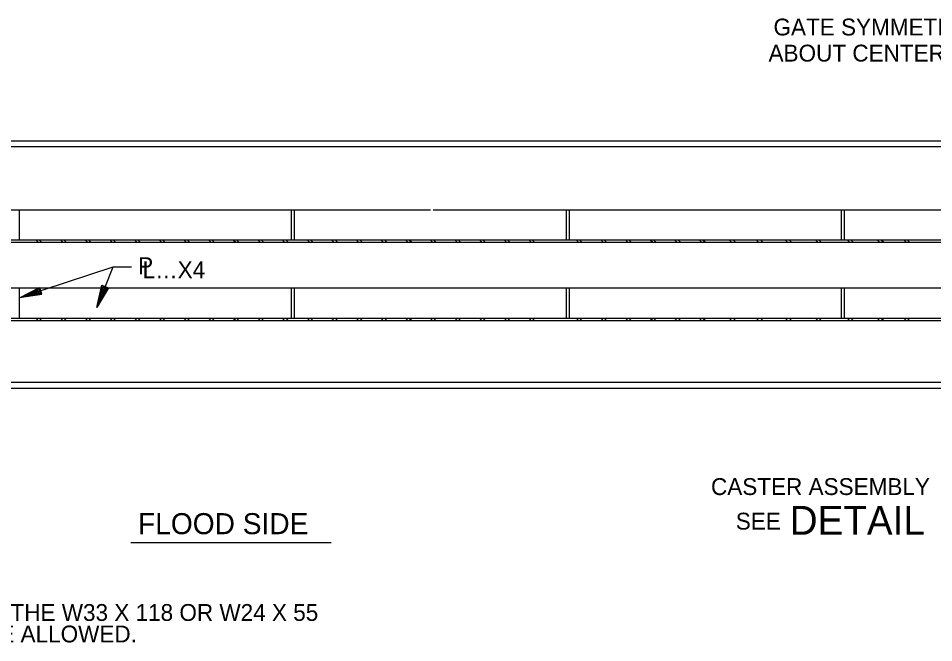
# Model space of a CAD drawing. Extents: x 0 to 53.3, y -2.9 to 37.3.
# Drawn here: x 33.49 to 43.64, y 11.84 to 18.76 of the extents above; entities that cross this region are included whole.
import ezdxf

# ---------------------------------------------------------------- set-up
doc = ezdxf.new("R2010")
doc.units = 0
for name, color, linetype in [('Level 2', 7, 'Continuous'), ('Level 25', 7, 'Continuous'), ('Level 3', 7, 'Continuous'), ('Level 44', 7, 'Continuous'), ('Level 50', 7, 'Continuous')]:
    doc.layers.add(name, color=color, linetype=linetype)

msp = doc.modelspace()

# ---------------------------------------------------------------- linework, layer by layer
at = {"layer": 'Level 2'}
for p, q in [((47.128, 17.401), (11.078, 17.401)), ((47.128, 17.338), (13.38, 17.338)), ((38.062, 16.635), (33.094, 16.635)), ((33.503, 16.302), (33.503, 16.635)), ((35.635, 16.635), (35.604, 16.635)), ((36.522, 16.302), (36.522, 16.635)), ((36.553, 16.302), (36.553, 16.635)), ((45.687, 16.635), (38.094, 16.635)), ((39.572, 16.302), (39.572, 16.635)), ((39.603, 16.302), (39.603, 16.635)), ((40.802, 16.635), (40.771, 16.635)), ((42.622, 16.302), (42.622, 16.635)), ((42.653, 16.302), (42.653, 16.635)), ((43.26, 16.635), (43.229, 16.635)), ((47.128, 16.302), (13.047, 16.302)), ((47.128, 16.276), (13.047, 16.276)), ((47.128, 15.77), (13.016, 15.77)), ((33.503, 15.436), (33.503, 15.77)), ((36.522, 15.436), (36.522, 15.77)), ((36.553, 15.436), (36.553, 15.77)), ((39.572, 15.436), (39.572, 15.77)), ((39.603, 15.436), (39.603, 15.77)), ((42.622, 15.436), (42.622, 15.77)), ((42.653, 15.436), (42.653, 15.77)), ((47.128, 15.436), (13.047, 15.436)), ((47.128, 15.41), (13.016, 15.41)), ((47.128, 14.724), (11.109, 14.724)), ((47.128, 14.661), (11.078, 14.661))]:
    msp.add_line(p, q, dxfattribs=at)
at = {"layer": 'Level 3'}
for p, q in [((34.54, 16.002), (34.362, 15.557)), ((34.362, 15.557), (34.362, 15.557)), ((34.388, 15.621), (34.388, 15.621))]:
    msp.add_line(p, q, dxfattribs=at)
msp.add_lwpolyline([(34.493, 15.773), (34.362, 15.557), (34.416, 15.804), (34.482, 15.778), (34.388, 15.621), (34.425, 15.789), (34.467, 15.772), (34.413, 15.683), (34.433, 15.774), (34.451, 15.767), (34.438, 15.748)], dxfattribs=at)
at = {"layer": 'Level 44'}
for p, q in [((33.715, 16.276), (33.689, 16.302)), ((33.753, 16.276), (33.727, 16.302)), ((33.988, 16.276), (33.962, 16.302)), ((34.026, 16.276), (34, 16.302)), ((34.262, 16.276), (34.236, 16.302)), ((34.3, 16.276), (34.274, 16.302)), ((34.535, 16.276), (34.509, 16.302)), ((34.573, 16.276), (34.547, 16.302)), ((34.809, 16.276), (34.783, 16.302)), ((34.846, 16.276), (34.82, 16.302)), ((35.082, 16.276), (35.056, 16.302)), ((35.12, 16.276), (35.094, 16.302)), ((35.356, 16.276), (35.329, 16.302)), ((35.393, 16.276), (35.367, 16.302)), ((35.629, 16.276), (35.603, 16.302)), ((35.667, 16.276), (35.641, 16.302)), ((35.902, 16.276), (35.876, 16.302)), ((35.94, 16.276), (35.914, 16.302)), ((36.176, 16.276), (36.15, 16.302)), ((36.213, 16.276), (36.187, 16.302)), ((36.449, 16.276), (36.423, 16.302)), ((36.487, 16.276), (36.461, 16.302)), ((36.723, 16.276), (36.697, 16.302)), ((36.76, 16.276), (36.734, 16.302)), ((36.996, 16.276), (36.97, 16.302)), ((37.034, 16.276), (37.008, 16.302)), ((37.269, 16.276), (37.243, 16.302)), ((37.307, 16.276), (37.281, 16.302)), ((37.543, 16.276), (37.517, 16.302)), ((37.581, 16.276), (37.555, 16.302)), ((37.816, 16.276), (37.79, 16.302)), ((37.854, 16.276), (37.828, 16.302)), ((38.09, 16.276), (38.064, 16.302)), ((38.127, 16.276), (38.101, 16.302)), ((38.363, 16.276), (38.337, 16.302)), ((38.401, 16.276), (38.375, 16.302)), ((38.637, 16.276), (38.61, 16.302)), ((38.674, 16.276), (38.648, 16.302)), ((38.91, 16.276), (38.884, 16.302)), ((38.948, 16.276), (38.922, 16.302)), ((39.183, 16.276), (39.157, 16.302)), ((39.221, 16.276), (39.195, 16.302)), ((39.707, 16.276), (39.681, 16.302)), ((39.744, 16.276), (39.718, 16.302)), ((39.98, 16.276), (39.954, 16.302)), ((40.018, 16.276), (39.992, 16.302)), ((40.254, 16.276), (40.228, 16.302)), ((40.291, 16.276), (40.265, 16.302)), ((40.527, 16.276), (40.501, 16.302)), ((40.565, 16.276), (40.539, 16.302)), ((40.8, 16.276), (40.774, 16.302)), ((40.838, 16.276), (40.812, 16.302)), ((41.074, 16.276), (41.048, 16.302)), ((41.112, 16.276), (41.085, 16.302)), ((41.406, 16.276), (41.38, 16.302)), ((41.45, 16.276), (41.424, 16.302)), ((41.703, 16.276), (41.677, 16.302)), ((41.753, 16.276), (41.727, 16.302)), ((42.025, 16.276), (41.999, 16.302)), ((42.069, 16.276), (42.043, 16.302)), ((42.364, 16.276), (42.338, 16.302)), ((42.398, 16.276), (42.372, 16.302)), ((42.715, 16.276), (42.689, 16.302)), ((42.755, 16.276), (42.729, 16.302)), ((43.047, 16.276), (43.021, 16.302)), ((43.089, 16.276), (43.063, 16.302)), ((43.342, 16.276), (43.315, 16.302)), ((43.378, 16.276), (43.352, 16.302)), ((34.54, 16.002), (33.503, 15.663)), ((34.748, 16.002), (34.54, 16.002)), ((33.715, 15.41), (33.689, 15.436)), ((33.753, 15.41), (33.727, 15.436)), ((33.988, 15.41), (33.962, 15.436)), ((34.026, 15.41), (34, 15.436)), ((34.262, 15.41), (34.236, 15.436)), ((34.3, 15.41), (34.274, 15.436)), ((34.535, 15.41), (34.509, 15.436)), ((34.573, 15.41), (34.547, 15.436)), ((34.809, 15.41), (34.783, 15.436)), ((34.846, 15.41), (34.82, 15.436)), ((35.082, 15.41), (35.056, 15.436)), ((35.12, 15.41), (35.094, 15.436)), ((35.356, 15.41), (35.329, 15.436)), ((35.393, 15.41), (35.367, 15.436)), ((35.629, 15.41), (35.603, 15.436)), ((35.667, 15.41), (35.641, 15.436)), ((35.902, 15.41), (35.876, 15.436)), ((35.94, 15.41), (35.914, 15.436)), ((36.176, 15.41), (36.15, 15.436)), ((36.213, 15.41), (36.187, 15.436)), ((36.449, 15.41), (36.423, 15.436)), ((36.487, 15.41), (36.461, 15.436)), ((36.723, 15.41), (36.697, 15.436)), ((36.76, 15.41), (36.734, 15.436)), ((36.996, 15.41), (36.97, 15.436)), ((37.034, 15.41), (37.008, 15.436)), ((37.269, 15.41), (37.243, 15.436)), ((37.307, 15.41), (37.281, 15.436)), ((37.543, 15.41), (37.517, 15.436)), ((37.581, 15.41), (37.555, 15.436)), ((37.816, 15.41), (37.79, 15.436)), ((37.854, 15.41), (37.828, 15.436)), ((38.09, 15.41), (38.064, 15.436)), ((38.127, 15.41), (38.101, 15.436)), ((38.363, 15.41), (38.337, 15.436)), ((38.401, 15.41), (38.375, 15.436)), ((38.637, 15.41), (38.61, 15.436)), ((38.674, 15.41), (38.648, 15.436)), ((38.91, 15.41), (38.884, 15.436)), ((38.948, 15.41), (38.922, 15.436)), ((39.183, 15.41), (39.157, 15.436)), ((39.221, 15.41), (39.195, 15.436)), ((39.707, 15.41), (39.681, 15.436)), ((39.744, 15.41), (39.718, 15.436)), ((39.98, 15.41), (39.954, 15.436)), ((40.018, 15.41), (39.992, 15.436)), ((40.254, 15.41), (40.228, 15.436)), ((40.291, 15.41), (40.265, 15.436)), ((40.527, 15.41), (40.501, 15.436)), ((40.565, 15.41), (40.539, 15.436)), ((40.8, 15.41), (40.774, 15.436)), ((40.838, 15.41), (40.812, 15.436)), ((41.074, 15.41), (41.048, 15.436)), ((41.112, 15.41), (41.085, 15.436)), ((41.406, 15.41), (41.38, 15.436)), ((41.45, 15.41), (41.424, 15.436)), ((41.703, 15.41), (41.677, 15.436)), ((41.753, 15.41), (41.727, 15.436)), ((42.025, 15.41), (41.999, 15.436)), ((42.069, 15.41), (42.043, 15.436)), ((42.364, 15.41), (42.338, 15.436)), ((42.398, 15.41), (42.372, 15.436)), ((42.715, 15.41), (42.689, 15.436)), ((42.755, 15.41), (42.729, 15.436)), ((43.047, 15.41), (43.021, 15.436)), ((43.089, 15.41), (43.063, 15.436)), ((43.342, 15.41), (43.315, 15.436)), ((43.378, 15.41), (43.352, 15.436))]:
    msp.add_line(p, q, dxfattribs=at)
at = {"layer": 'Level 50'}
for p, q in [((33.503, 15.663), (33.503, 15.663)), ((33.569, 15.684), (33.569, 15.684)), ((36.961, 12.949), (34.738, 12.949))]:
    msp.add_line(p, q, dxfattribs=at)
msp.add_lwpolyline([(33.753, 15.701), (33.503, 15.663), (33.727, 15.779), (33.749, 15.712), (33.569, 15.684), (33.721, 15.763), (33.735, 15.72), (33.632, 15.705), (33.715, 15.747), (33.721, 15.73), (33.698, 15.726)], dxfattribs=at)

# ---------------------------------------------------------------- texts
at = {"layer": 'Level 25'}
for s, p in [('NO SPLICING OF THE W33 X 118 OR W24 X 55', (31.31, 12.084)), ('BEAMS SHALL BE ALLOWED.', (31.31, 11.846))]:
    msp.add_text(s, height=0.1867, dxfattribs=at).set_placement(p)
at = {"layer": 'Level 3'}
msp.add_text('DETAIL', height=0.32, dxfattribs=at).set_placement((42.047, 13.038))
at = {"layer": 'Level 44'}
for s, height, p in [('GATE SYMMETRICAL', 0.1867, (41.867, 18.571)), ('ABOUT CENTER LINE', 0.1867, (41.812, 18.282)), ('P', 0.187, (34.82, 15.926)), ('L…X4 ', 0.1867, (34.87, 15.881))]:
    msp.add_text(s, height=height, dxfattribs=at).set_placement(p)
at = {"layer": 'Level 50'}
for s, height, p in [('CASTER ASSEMBLY', 0.1867, (41.174, 13.479)), ('FLOOD SIDE', 0.2333, (34.819, 13.045)), ('SEE', 0.1867, (41.449, 13.096))]:
    msp.add_text(s, height=height, dxfattribs=at).set_placement(p)

doc.saveas('drawing.dxf')
